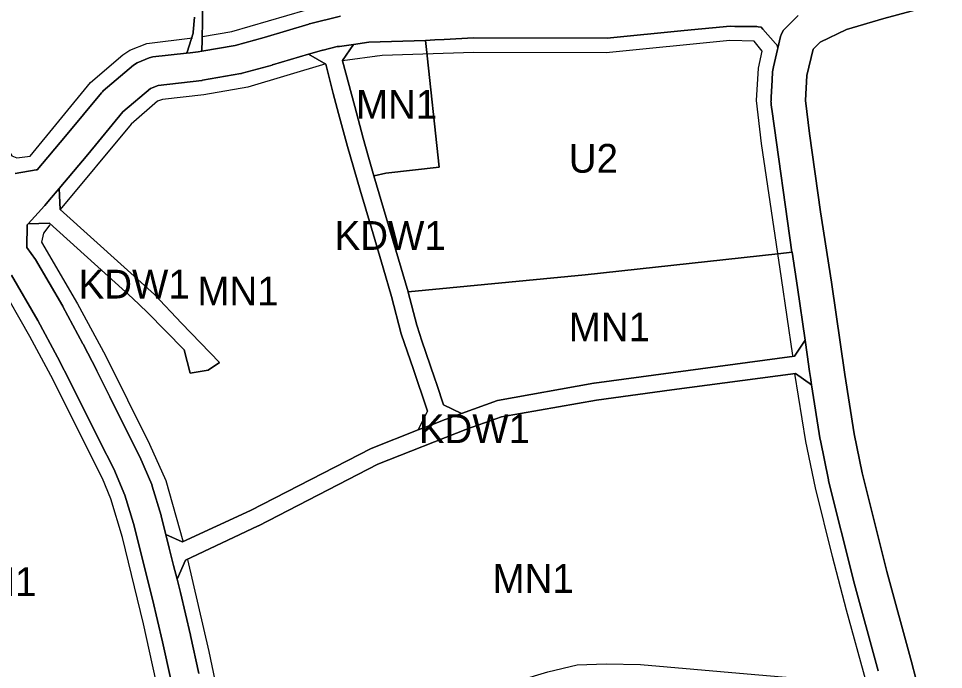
# Model space of a CAD drawing. Extents: x -284239 to -281592, y 34477 to 37267.
# Drawn here: x -282543.7 to -282222.1, y 35175.9 to 35402.1 of the extents above; entities that cross this region are included whole.
import ezdxf

# ---------------------------------------------------------------- set-up
doc = ezdxf.new("R2010")
doc.units = 0
for name, color, linetype in [('linie_rozgraniczajace', 7, 'Continuous'), ('linie_zabudowy_nieprzekraczalne', 7, 'Continuous'), ('oznaczenia_przeznaczen', 7, 'Continuous')]:
    doc.layers.add(name, color=color, linetype=linetype)

msp = doc.modelspace()

# ---------------------------------------------------------------- linework, layer by layer
at = {"layer": 'linie_rozgraniczajace'}
for points in [[(-282479.674, 35405.571), (-282479.674, 35401.469), (-282479.838, 35394.824), (-282479.974, 35390.704), (-282481.257, 35390.48), (-282484.052, 35390.165), (-282485.264, 35390.028), (-282485.01, 35390.429), (-282482.957, 35397.016), (-282482.916, 35397.302), (-282482.521, 35402.543)], [(-282431.773, 35402.86), (-282442.517, 35400.234), (-282442.69, 35400.177), (-282442.767, 35400.166), (-282458.232, 35395.526), (-282468.333, 35392.74), (-282479.974, 35390.704), (-282479.838, 35394.824), (-282479.674, 35401.469), (-282479.674, 35405.571)], [(-282270.064, 35373.552), (-282269.555, 35382.306), (-282267.449, 35391.369), (-282264.917, 35393.837), (-282255.76, 35398.216), (-282242.854, 35402.044), (-282222.092, 35407.604)], [(-282222.092, 35407.604), (-282242.854, 35402.044), (-282255.76, 35398.216), (-282264.917, 35393.837), (-282267.449, 35391.369), (-282269.555, 35382.306), (-282270.064, 35373.552), (-282268.711, 35362.137), (-282264.798, 35334.86), (-282260.989, 35310.47), (-282260.982, 35310.412), (-282256.372, 35278.385), (-282253.097, 35257.717), (-282250.359, 35244.25), (-282241.81, 35209.883), (-282233.229, 35178.566), (-282233.212, 35178.508), (-282228.681, 35161.146)], [(-282482.521, 35402.543), (-282482.916, 35397.302), (-282482.957, 35397.016), (-282485.01, 35390.429), (-282485.264, 35390.028), (-282496.983, 35388.706), (-282498.314, 35388.364), (-282502.39, 35386.688), (-282503.725, 35385.872), (-282514.23, 35376.919), (-282514.523, 35376.649), (-282514.842, 35376.297), (-282527.299, 35361.217), (-282537.244, 35349.443), (-282537.511, 35349.521), (-282544.893, 35348.256)], [(-282272.586, 35403.12), (-282277.68, 35397.974), (-282278.439, 35396.735), (-282278.74, 35395.797), (-282279.678, 35391.76), (-282279.903, 35392.661), (-282279.935, 35392.793), (-282280.502, 35393.427), (-282284.881, 35398.325), (-282285.537, 35399.058), (-282286.484, 35399.212), (-282287.008, 35399.27), (-282289.982, 35399.302), (-282289.985, 35399.303), (-282294.619, 35399.353), (-282296.286, 35399.368), (-282296.295, 35399.367), (-282312.303, 35397.912), (-282338.989, 35395.265), (-282385.517, 35395.33), (-282395.734, 35394.737), (-282398.984, 35394.625), (-282402.19, 35394.457), (-282421.937, 35393.83), (-282427.194, 35393.093), (-282432.143, 35392.4), (-282432.871, 35392.298), (-282437.774, 35391.099), (-282437.979, 35391.049), (-282440.017, 35390.551), (-282442.833, 35389.706), (-282455.412, 35385.932), (-282455.443, 35385.928), (-282455.519, 35385.901), (-282465.905, 35383.036), (-282466.104, 35383.01), (-282466.374, 35382.931), (-282479.684, 35380.603), (-282479.885, 35380.586), (-282479.985, 35380.56), (-282495.167, 35378.848), (-282497.843, 35377.746), (-282507.411, 35369.591), (-282519.607, 35354.828), (-282519.639, 35354.791), (-282529.602, 35342.992), (-282532.937, 35339.044), (-282534.564, 35337.118), (-282534.662, 35337.008), (-282536.9, 35334.52), (-282540.344, 35330.695), (-282540.676, 35330.326), (-282540.78, 35322.63), (-282540.813, 35322.498), (-282537.782, 35318.32), (-282528.326, 35302.1), (-282528.274, 35301.995), (-282528.247, 35301.959)], [(-282502.39, 35386.688), (-282498.314, 35388.364), (-282496.983, 35388.706), (-282485.264, 35390.028), (-282484.052, 35390.165), (-282481.257, 35390.48), (-282479.974, 35390.704), (-282468.333, 35392.74), (-282458.232, 35395.526), (-282442.767, 35400.166), (-282442.69, 35400.177), (-282442.517, 35400.234), (-282431.773, 35402.86)], [(-282282.084, 35373.372), (-282282.063, 35373.478), (-282282.065, 35373.669), (-282282.018, 35374.683), (-282282.018, 35374.688), (-282281.674, 35380.593), (-282281.619, 35381.549), (-282281.557, 35382.622), (-282281.505, 35383.513), (-282281.498, 35383.543), (-282281.404, 35384.135), (-282281.323, 35384.679), (-282281.187, 35385.266), (-282279.786, 35391.294), (-282279.68, 35391.752), (-282279.678, 35391.76), (-282278.74, 35395.797), (-282278.439, 35396.735), (-282277.68, 35397.974), (-282272.586, 35403.12)], [(-282544.893, 35348.256), (-282537.511, 35349.521), (-282537.244, 35349.443), (-282527.299, 35361.217), (-282514.842, 35376.297), (-282514.523, 35376.649), (-282514.23, 35376.919), (-282503.725, 35385.872), (-282502.39, 35386.688)], [(-282244.814, 35175.442), (-282253.402, 35206.78), (-282253.408, 35206.828), (-282253.438, 35206.917), (-282262.035, 35241.479), (-282262.049, 35241.589), (-282262.093, 35241.731), (-282264.883, 35255.453), (-282264.897, 35255.596), (-282264.929, 35255.71), (-282267.951, 35274.782), (-282268.231, 35276.549), (-282268.235, 35276.602), (-282268.244, 35276.634), (-282268.643, 35279.404), (-282269.497, 35285.343), (-282270.213, 35290.321), (-282272.851, 35308.654), (-282274.757, 35320.857), (-282274.765, 35320.912), (-282281.696, 35369.74), (-282281.881, 35371.306), (-282281.977, 35372.112), (-282282.056, 35372.894), (-282282.084, 35373.372)], [(-282228.681, 35161.146), (-282233.212, 35178.508), (-282233.229, 35178.566), (-282241.81, 35209.883), (-282250.359, 35244.25), (-282253.097, 35257.717), (-282256.372, 35278.385), (-282260.982, 35310.412), (-282260.989, 35310.47), (-282264.798, 35334.86), (-282268.711, 35362.137), (-282270.064, 35373.552)], [(-282546.171, 35312.91), (-282537.013, 35297.146), (-282530.123, 35284.351), (-282525.422, 35275.176), (-282515.543, 35255.372), (-282510.592, 35245.61), (-282506.662, 35236.471), (-282503.721, 35226.637), (-282497.121, 35200.281), (-282493.649, 35185.49), (-282490.701, 35172.369), (-282488.867, 35163.617), (-282525.01, 35155.389), (-282533.9, 35152.937), (-282530.528, 35136.381), (-282528.402, 35122.716), (-282541.458, 35123.137), (-282556.202, 35125.799)], [(-282490.701, 35172.369), (-282493.649, 35185.49), (-282497.121, 35200.281), (-282503.721, 35226.637), (-282506.662, 35236.471), (-282510.592, 35245.61), (-282515.543, 35255.372), (-282525.422, 35275.176), (-282530.123, 35284.351), (-282537.013, 35297.146), (-282546.171, 35312.91)], [(-282528.247, 35301.959), (-282521.294, 35289.047), (-282521.253, 35288.966), (-282516.51, 35279.712), (-282516.488, 35279.667), (-282511.967, 35270.604), (-282506.609, 35259.862), (-282501.602, 35249.992), (-282501.57, 35249.855), (-282501.468, 35249.706), (-282497.362, 35240.156), (-282497.355, 35240.122), (-282497.335, 35240.094), (-282497.164, 35239.613), (-282494.108, 35229.394), (-282494.099, 35229.328), (-282494.049, 35229.176), (-282492.457, 35222.822), (-282491.255, 35218.022), (-282489.743, 35211.985), (-282488.549, 35207.216), (-282487.411, 35202.674), (-282487.408, 35202.646), (-282487.394, 35202.602), (-282483.907, 35187.742), (-282483.897, 35187.705), (-282480.937, 35174.526)], [(-282480.937, 35174.526), (-282483.897, 35187.705), (-282483.907, 35187.742), (-282487.394, 35202.602), (-282487.408, 35202.646), (-282487.411, 35202.674), (-282488.549, 35207.216), (-282488.473, 35207.273), (-282485.627, 35213.913), (-282460.383, 35225.744), (-282460.28, 35225.794), (-282418.761, 35247.182), (-282387.596, 35259.544), (-282375.729, 35263.712), (-282342.692, 35269.47), (-282316.567, 35273.079), (-282273.525, 35278.759), (-282267.951, 35274.782), (-282264.929, 35255.71), (-282264.897, 35255.596), (-282264.883, 35255.453), (-282262.093, 35241.731), (-282262.049, 35241.589), (-282262.035, 35241.479), (-282253.438, 35206.917), (-282253.408, 35206.828), (-282253.402, 35206.78), (-282244.814, 35175.442)]]:
    msp.add_lwpolyline(points, dxfattribs=at)
for points in [[(-282420.1, 35347.42), (-282420.065, 35347.428), (-282416, 35348.34), (-282397.46, 35350.44), (-282401.96, 35392.32), (-282402.19, 35394.457), (-282398.984, 35394.625), (-282395.734, 35394.737), (-282385.517, 35395.33), (-282338.989, 35395.265), (-282312.303, 35397.912), (-282296.295, 35399.367), (-282296.286, 35399.368), (-282294.619, 35399.353), (-282289.985, 35399.303), (-282289.982, 35399.302), (-282287.008, 35399.27), (-282286.484, 35399.212), (-282285.537, 35399.058), (-282284.881, 35398.325), (-282280.502, 35393.427), (-282279.935, 35392.793), (-282279.903, 35392.661), (-282279.678, 35391.76), (-282279.68, 35391.752), (-282279.786, 35391.294), (-282281.187, 35385.266), (-282281.323, 35384.679), (-282281.404, 35384.135), (-282281.498, 35383.543), (-282281.505, 35383.513), (-282281.557, 35382.622), (-282281.619, 35381.549), (-282281.674, 35380.593), (-282282.018, 35374.688), (-282282.018, 35374.683), (-282282.065, 35373.669), (-282282.063, 35373.478), (-282282.084, 35373.372), (-282282.056, 35372.894), (-282281.977, 35372.112), (-282281.881, 35371.306), (-282281.696, 35369.74), (-282274.765, 35320.912), (-282274.757, 35320.857), (-282279.676, 35320.323), (-282346.693, 35313.047), (-282408.225, 35307.042), (-282408.24, 35307.04)], [(-282442.833, 35389.706), (-282440.017, 35390.551), (-282437.979, 35391.049), (-282437.774, 35391.099), (-282432.871, 35392.298), (-282432.143, 35392.4), (-282427.194, 35393.093), (-282431.092, 35387.522), (-282431.057, 35387.36), (-282426.793, 35371.495), (-282423.812, 35360.445), (-282421.978, 35353.842), (-282420.1, 35347.42), (-282408.24, 35307.04), (-282408.225, 35307.042), (-282408.223, 35307.034), (-282405.242, 35295.518), (-282405.117, 35295.134), (-282403.454, 35290.016), (-282399.098, 35277.268), (-282398.265, 35274.848), (-282395.907, 35267.867), (-282395.878, 35267.852), (-282389.657, 35264.815), (-282394.358, 35263.095), (-282395.688, 35262.608), (-282399.969, 35260.939), (-282404.681, 35259.103), (-282401.494, 35265.683), (-282401.711, 35266.31), (-282406.388, 35280.065), (-282410.607, 35292.492), (-282414, 35305.514), (-282416.888, 35315.418), (-282420.924, 35329.265), (-282424.867, 35342.471), (-282429.36, 35357.602), (-282432.387, 35369.019), (-282434.267, 35375.989), (-282436.784, 35386.2)], [(-282431.092, 35387.522), (-282427.194, 35393.093), (-282421.937, 35393.83), (-282402.19, 35394.457), (-282401.96, 35392.32), (-282397.46, 35350.44), (-282416, 35348.34), (-282420.065, 35347.428), (-282420.1, 35347.42), (-282421.978, 35353.842), (-282423.812, 35360.445), (-282426.793, 35371.495), (-282431.057, 35387.36)], [(-282540.813, 35322.498), (-282540.78, 35322.63), (-282540.676, 35330.326), (-282540.344, 35330.695), (-282532.944, 35330.948), (-282504.087, 35304.887), (-282498.927, 35299.992), (-282486.095, 35286.895), (-282483.978, 35278.825), (-282477.761, 35279.883), (-282473.792, 35282.529), (-282487.021, 35296.155), (-282496.414, 35306.209), (-282529.229, 35335.71), (-282529.602, 35342.992), (-282519.639, 35354.791), (-282519.607, 35354.828), (-282507.411, 35369.591), (-282497.843, 35377.746), (-282495.167, 35378.848), (-282479.985, 35380.56), (-282479.885, 35380.586), (-282479.684, 35380.603), (-282466.374, 35382.931), (-282466.104, 35383.01), (-282465.905, 35383.036), (-282455.519, 35385.901), (-282455.443, 35385.928), (-282455.412, 35385.932), (-282442.833, 35389.706), (-282436.784, 35386.2), (-282434.267, 35375.989), (-282432.387, 35369.019), (-282429.36, 35357.602), (-282424.867, 35342.471), (-282420.924, 35329.265), (-282416.888, 35315.418), (-282414, 35305.514), (-282410.607, 35292.492), (-282406.388, 35280.065), (-282401.711, 35266.31), (-282401.494, 35265.683), (-282404.681, 35259.103), (-282421.111, 35252.698), (-282462.973, 35231.155), (-282486.631, 35220.169), (-282486.734, 35220.267), (-282492.457, 35222.822), (-282494.049, 35229.176), (-282494.099, 35229.328), (-282494.108, 35229.394), (-282497.164, 35239.613), (-282497.335, 35240.094), (-282497.355, 35240.122), (-282497.362, 35240.156), (-282501.468, 35249.706), (-282501.57, 35249.855), (-282501.602, 35249.992), (-282506.609, 35259.862), (-282511.967, 35270.604), (-282516.488, 35279.667), (-282516.51, 35279.712), (-282521.253, 35288.966), (-282521.294, 35289.047), (-282528.247, 35301.959), (-282528.274, 35301.995), (-282528.326, 35302.1), (-282537.782, 35318.32)], [(-282540.344, 35330.695), (-282536.9, 35334.52), (-282534.662, 35337.008), (-282534.564, 35337.118), (-282532.937, 35339.044), (-282529.602, 35342.992), (-282529.229, 35335.71), (-282496.414, 35306.209), (-282487.021, 35296.155), (-282473.792, 35282.529), (-282477.761, 35279.883), (-282483.978, 35278.825), (-282486.095, 35286.895), (-282498.927, 35299.992), (-282504.087, 35304.887), (-282532.944, 35330.948)], [(-282408.225, 35307.042), (-282346.693, 35313.047), (-282279.676, 35320.323), (-282274.757, 35320.857), (-282272.851, 35308.654), (-282270.213, 35290.321), (-282273.917, 35284.76), (-282343.577, 35275.405), (-282343.673, 35275.387), (-282377.162, 35269.288), (-282389.657, 35264.815), (-282395.878, 35267.852), (-282395.907, 35267.867), (-282398.265, 35274.848), (-282399.098, 35277.268), (-282403.454, 35290.016), (-282405.117, 35295.134), (-282405.242, 35295.518), (-282408.223, 35307.034)], [(-282492.457, 35222.822), (-282486.734, 35220.267), (-282486.631, 35220.169), (-282462.973, 35231.155), (-282421.111, 35252.698), (-282404.681, 35259.103), (-282399.969, 35260.939), (-282395.688, 35262.608), (-282394.358, 35263.095), (-282389.657, 35264.815), (-282377.162, 35269.288), (-282343.673, 35275.387), (-282343.577, 35275.405), (-282273.917, 35284.76), (-282270.213, 35290.321), (-282269.497, 35285.343), (-282268.643, 35279.404), (-282268.244, 35276.634), (-282268.235, 35276.602), (-282268.231, 35276.549), (-282267.951, 35274.782), (-282273.525, 35278.759), (-282316.567, 35273.079), (-282342.692, 35269.47), (-282375.729, 35263.712), (-282387.596, 35259.544), (-282418.761, 35247.182), (-282460.28, 35225.794), (-282460.383, 35225.744), (-282485.627, 35213.913), (-282488.473, 35207.273), (-282488.549, 35207.216), (-282489.743, 35211.985), (-282491.255, 35218.022)]]:
    msp.add_lwpolyline(points, close=True, dxfattribs=at)
at = {"layer": 'linie_zabudowy_nieprzekraczalne'}
for points in [[(-282452.498, 35611.149), (-282508.316, 35599.405), (-282545.754, 35589.681), (-282587.823, 35578.569), (-282589.543, 35575.262), (-282583.458, 35539.08), (-282574.462, 35485.303), (-282568.244, 35452.362), (-282560.571, 35414.064), (-282549.855, 35360.486), (-282546.019, 35354.4), (-282544.299, 35353.606), (-282539.669, 35354.268), (-282518.634, 35379.8), (-282507.39, 35389.457), (-282505.008, 35391.045), (-282499.055, 35393.426), (-282483.18, 35395.411)], [(-282479.741, 35395.808), (-282469.554, 35397.527), (-282444.022, 35404.936), (-282433.042, 35407.78), (-282426.03, 35408.706), (-282397.984, 35409.5), (-282392.041, 35409.536)], [(-282274.433, 35284.917), (-282278.392, 35311.868), (-282285.404, 35358.633), (-282287.124, 35373.582), (-282286.462, 35384.827), (-282285.139, 35390.78), (-282287.917, 35394.22), (-282296.384, 35394.418), (-282339.379, 35390.185), (-282385.417, 35390.317), (-282417.308, 35389.185), (-282431.057, 35387.36)], [(-282419.291, 35388.999), (-282419.416, 35388.994)], [(-282436.811, 35386.312), (-282463.998, 35378.213), (-282479.211, 35375.567), (-282493.631, 35373.979), (-282495.351, 35373.318), (-282504.479, 35365.38), (-282529.227, 35335.717)], [(-282524.436, 35341.459), (-282524.455, 35341.436)], [(-282532.799, 35330.425), (-282535.048, 35327.515), (-282535.71, 35324.34), (-282523.132, 35302.939), (-282513.475, 35285.013), (-282498.129, 35254.189), (-282492.441, 35241.489), (-282486.497, 35220.623)], [(-282529.086, 35048.012), (-282511.358, 35045.234), (-282491.118, 35042.323), (-282488.604, 35044.308), (-282485.297, 35064.284), (-282485.429, 35077.844), (-282487.281, 35091.073), (-282487.281, 35117.399), (-282487.017, 35124.741), (-282492.044, 35153.846), (-282493.764, 35162.246), (-282500.246, 35191.681), (-282507.522, 35221.711), (-282511.623, 35235.205), (-282514.533, 35242.283), (-282532.393, 35278.002), (-282539.801, 35291.628), (-282550.385, 35310.148)], [(-282484.91, 35214.141), (-282477.492, 35182.09), (-282469.157, 35142.27), (-282466.379, 35140.087), (-282445.874, 35140.352), (-282436.349, 35141.41), (-282421.135, 35146.57), (-282411.875, 35150.538), (-282395.735, 35161.188), (-282385.946, 35165.95), (-282379.596, 35168.596), (-282369.277, 35172.168), (-282359.62, 35175.078), (-282349.433, 35177.46), (-282339.379, 35177.857), (-282327.473, 35177.658), (-282290.299, 35174.351), (-282249.817, 35170.911), (-282249.024, 35171.705), (-282255.77, 35196.444), (-282260.665, 35215.163), (-282266.618, 35238.975), (-282269.926, 35255.115), (-282273.772, 35278.699)]]:
    msp.add_lwpolyline(points, dxfattribs=at)

# ---------------------------------------------------------------- texts
at = {"layer": 'oznaczenia_przeznaczen'}
for s, p in [('MN1', (-282426.353, 35367.238)), ('U2', (-282352.363, 35348.492)), ('KDW1', (-282433.775, 35321.678)), ('KDW1', (-282522.791, 35304.778)), ('MN1', (-282481.493, 35302.374)), ('MN1', (-282352.367, 35289.914)), ('KDW1', (-282404.481, 35254.544)), ('MN1', (-282378.874, 35202.501)), ('MN1', (-282565.686, 35201.382))]:
    msp.add_text(s, height=10, dxfattribs=at).set_placement(p)

doc.saveas('drawing.dxf')
